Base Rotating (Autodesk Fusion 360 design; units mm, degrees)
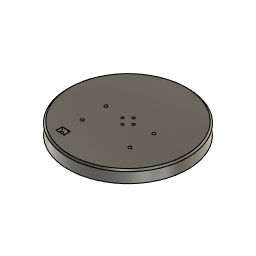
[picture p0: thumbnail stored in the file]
sketch "Sketch1" plane through (0, 0, 0) normal (0, 0, 1) x axis (1, 0, 0)
  line L1 (-37.5, 15) -> (-37.5, -40)
  line L2 (22.5, 10.5) -> (17.5, 10.5)
  line L3 (17.5, -10.5) -> (22.5, -10.5)
  line L4 (17.5, 0) -> (22.5, 0)
  line L5 (22.5, -10.5) -> (22.5, 10.5)
  line L6 (37.5, 15) -> (17.5, 15)
  line L7 (-17.5, 0) -> (17.5, 0)
  line L8 (-17.5, -40) -> (-17.5, 15)
  line L9 (37.5, -40) -> (37.5, 15)
  line L10 (17.5, 10.5) -> (17.5, -10.5)
  line L11 (0, -17.8635) -> (0, 0)
  line L12 (-17.5, 15) -> (-37.5, 15)
  line L13 (17.5, -40) -> (37.5, -40)
  line L14 (-37.5, -40) -> (-17.5, -40)
  line L15 (17.5, 15) -> (17.5, -40)
  circle C1 centre (0, 0) radius 75
  circle C2 centre (-30, 2.5) radius 1.85
  circle C3 centre (-30, -27.5) radius 1.85
  circle C4 centre (30, -27.5) radius 1.85
  circle C5 centre (30, 2.5) radius 1.85
  circle C6 centre (7, 0) radius 1.55
  circle C7 centre (0, 7) radius 1.55
  circle C8 centre (-7, 0) radius 1.55
  circle C9 centre (0, -7) radius 1.55
  point P1 (0, 0)
  point P2 (0, 0)
  point P22 (-17.5, 0)
  point P24 (0, 0)
  point P26 (7, 0)
  point P8 (-30, 2.5)
  point P5 (30, 2.5)
  point P9 (30, -27.5)
  point P21 (-30, -27.5)
  coincident P1 P2
  coincident P22 L8
  perpendicular L7 L8
  midpoint P24 L7
  perpendicular L7 L11
  coincident L7 P26
  dimension "d1" diameter C1 = 150
  dimension "d15" diameter C6 = 3.1
  dimension "d16" distance P2 P26 = 7
  dimension "d19" diameter C5 = 3.7
  dimension "d20" diameter C4 = 3.7 (= "d19")
  dimension "d21" diameter C3 = 3.7 (= "d19")
  dimension "d22" diameter C2 = 3.7 (= "d19")
  dimension "d36" distance P2 P8 = 30
  dimension "d38" distance P5 P8 = 60
  dimension "d39" distance P9 P21 = 60
  dimension "d40" distance P5 P9 = 30
  dimension "d41" distance P8 P21 = 30
  dimension "d18" C-Pattern1-Angle = 360
extrude "Extrude1" new body sketch "Sketch1" profile of C1 C2 C3 C4 C5 C6 C7 C8 C9 along normal blind 5
sketch "Sketch2" plane through (0, 0, 0) normal (0, 0, -1) x axis (1, 0, 0)
  circle C1 centre (-30, 27.5) radius 1.85
  circle C2 centre (30, -2.5) radius 1.85
  circle C3 centre (30, 27.5) radius 1.85
  circle C4 centre (-30, -2.5) radius 1.85
  circle C5 centre (0, 0) radius 75
  circle C6 centre (0, 0) radius 70
  circle C7 centre (-7, 0) radius 1.55
  circle C8 centre (0, -7) radius 1.55
  circle C9 centre (7, 0) radius 1.55
  circle C10 centre (0, 7) radius 1.55
  dimension "d4" diameter C6 = 140 (= "d7 - 10 mm")
  dimension "d7" diameter C5 = 150
extrude "Extrude2" add sketch "Sketch2" profile of C5 C6 along normal blind 10
chamfer "Chamfer1" distance 1
sketch "Sketch4" plane through (0, 0, 5) normal (0, 0, 1) x axis (-1, 0, 0)
  line L1 (30, 52.5) -> (30, -2.5)
  line L2 (27.5, 52.5) -> (30, 52.5)
  line L3 (27.5, 47.5) -> (27.5, 52.5)
  line L4 (30, 47.5) -> (27.5, 47.5)
  line L5 (30, 52.5) -> (30, 47.5)
  line L6 (25, 47.5) -> (30, 47.5)
  line L7 (25, 55) -> (25, 47.5)
  line L8 (30, 55) -> (25, 55)
  line L9 (30, 47.5) -> (30, 55)
  line L10 (35, 47.5) -> (30, 47.5)
  line L11 (30, 52.5) -> (30, 47.5)
  line L12 (32.5, 52.5) -> (30, 52.5)
  line L13 (32.5, 47.5) -> (32.5, 52.5)
  line L14 (30, 47.5) -> (32.5, 47.5)
  line L15 (35, 55) -> (35, 47.5)
  line L16 (30, 47.5) -> (30, 55)
  line L17 (30, 55) -> (35, 55)
  circle C1 centre (0, 7) radius 1.55
  circle C2 centre (-30, 27.5) radius 1.85
  circle C3 centre (30, 27.5) radius 1.85
  circle C4 centre (-30, -2.5) radius 1.85
  circle C5 centre (7, 0) radius 1.55
  circle C6 centre (-7, 0) radius 1.55
  circle C7 centre (0, -7) radius 1.55
  circle C8 centre (30, -2.5) radius 1.85
  circle C9 centre (0, 0) radius 75
  point P9 (30, -2.5)
  point P11 (30, -2.5)
  point P12 (30, 52.5)
  point P20 (30, 52.5)
  point P13 (27.5, 52.5)
  point P22 (32.5, 52.5)
  point P14 (27.5, 47.5)
  point P23 (32.5, 47.5)
  point P15 (30, 47.5)
  point P25 (30, 47.5)
  point P16 (25, 47.5)
  point P21 (35, 47.5)
  point P17 (25, 55)
  point P24 (35, 55)
  point P18 (30, 55)
  point P19 (30, 55)
  point P4 (30, 27.5)
  coincident P9 P11
  vertical L1
  horizontal L2
  vertical L3
  horizontal L4
  vertical L5
  horizontal L6
  vertical L7
  horizontal L8
  vertical L9
  symmetric P12 L1 P20
  symmetric L1 P13 P22
  symmetric L1 P14 P23
  symmetric L1 P15 P25
  symmetric L1 P16 P21
  symmetric L1 P17 P24
  symmetric L1 P18 P19
  dimension "d23" distance P12 P13 = 2.5
  dimension "d24" distance P12 P15 = 5
  dimension "d25" distance P15 P16 = 5 (= "d23 * 2")
  dimension "d26" distance P15 P18 = 7.5 (= "d23 * 3")
  dimension "d35" distance P4 L6 = 20
extrude "Extrude3" cut sketch "Sketch4" profile of L2 L3 L6 L7 L8 L9 L10 L12 L13 L15 L16 L17 to an object
sketch "Sketch5" plane through (0, -52.5, 0) normal (0, -1, 0) x axis (1, 0, 0)
  line L1 (-27.5, 0) -> (-32.5, 0)
  line L2 (-27.5, 5) -> (-27.5, 0)
  line L3 (-32.5, 5) -> (-27.5, 5)
  line L4 (-32.5, 0) -> (-32.5, 5)
  circle C1 centre (-30, 2.5) radius 2.5
  point P6 (-30, 2.5)
  point P4 (-27.5, 5)
  point P5 (-32.5, 5)
  dimension "d30" distance L3 P6 = 2.5 (= "d31 / 2")
  dimension "d31" distance P4 P5 = 5
  dimension "d32" diameter C1 = 5 (= "d31")
extrude "Extrude4" cut sketch "Sketch5" against normal blind 5
chamfer "Chamfer2" distance 2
